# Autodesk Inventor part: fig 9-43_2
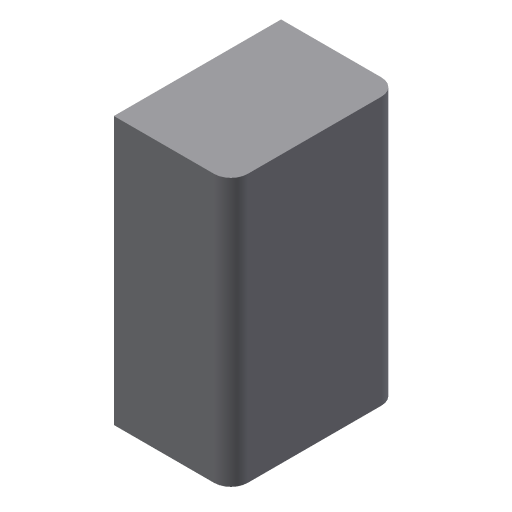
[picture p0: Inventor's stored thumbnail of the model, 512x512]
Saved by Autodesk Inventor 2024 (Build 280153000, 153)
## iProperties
Created: 2013-03
Part Number: fig 9-43_2
Material: Generic
Document SubType Name: Modeling
Designer: CADCIM
Density: 1 g/cm^3
Appearance: Default
Author: CADCIM
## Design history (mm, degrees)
sketch "Sketch1"
  geometry: L1 (-2.508, 1.862)-(2.492, 1.862); L2 (2.492, 1.862)-(2.492, -6.138); L3 (2.492, -6.138)-(-2.508, -6.138); L4 (-2.508, -6.138)-(-2.508, 1.862); 1 further point
  constraints: 8 end point, 2 parallel, 1 horizontal, 1 perpendicular
  dimensions: "d0" = 5 distance of L1.start L1.end; "d2" = 8 distance of L1.end L2.end
extrude "Extrusion1" new body sketch "Sketch1" distance "d3" = 3.5; taper "d4" = 0 deg
fillet "Fillet1" dims "d5" = 0.5
fillet "Fillet2" dims "d6" = 0.5
body "Solid1"
